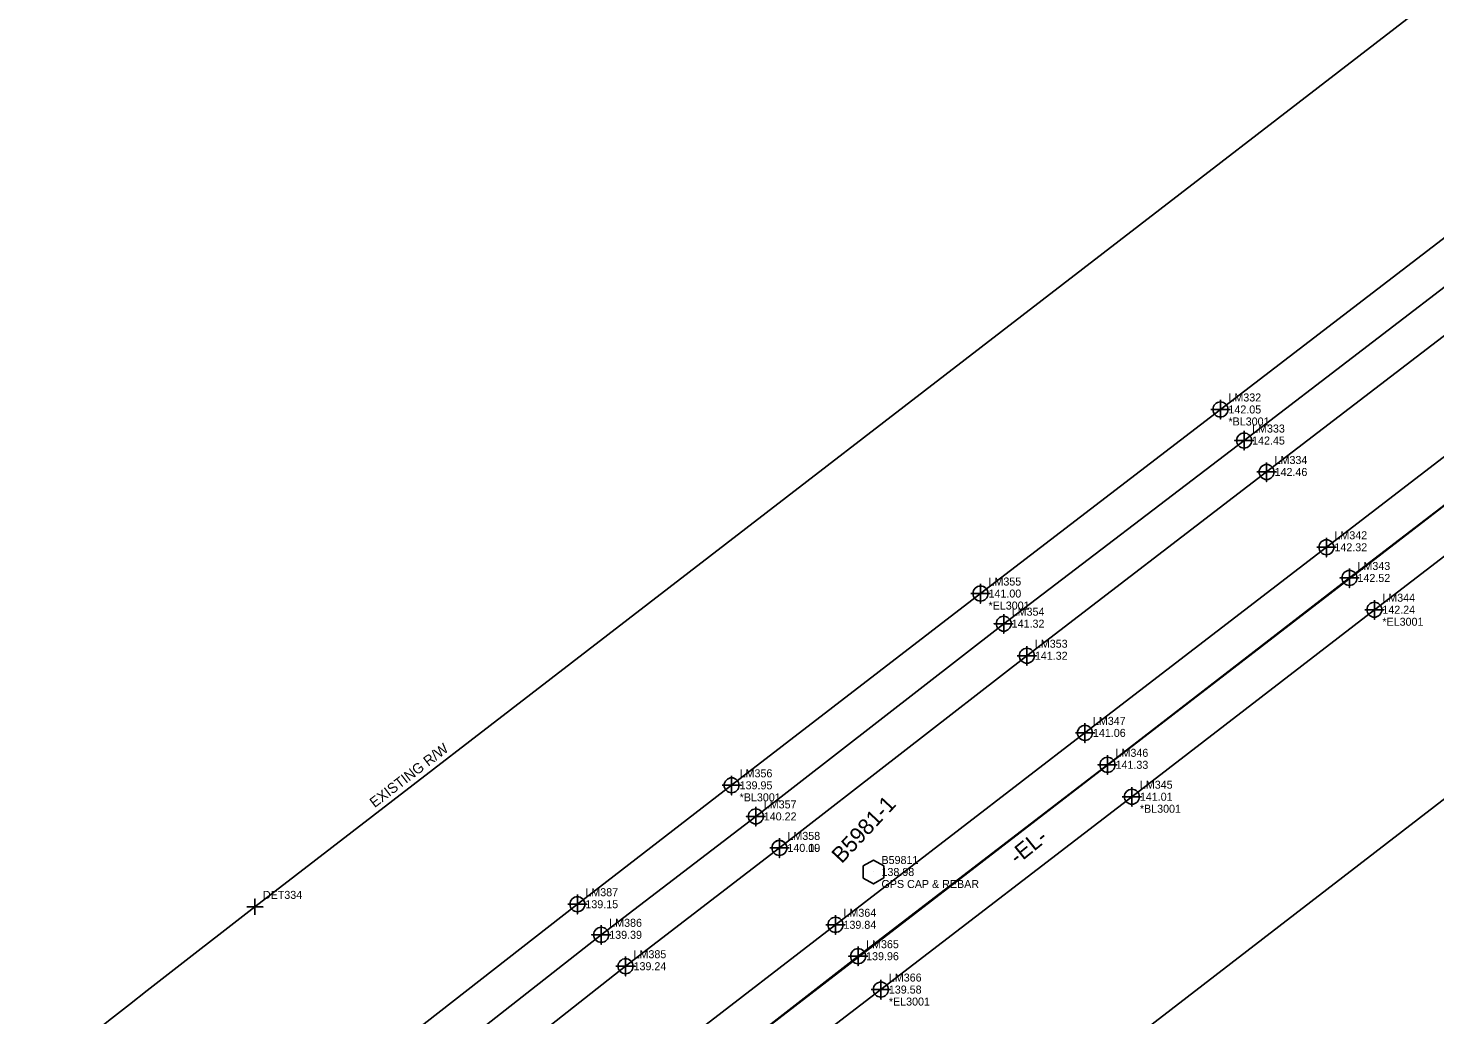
# Model space of a CAD drawing. Extents: x 2262665 to 2270527, y 505476 to 514960.
# Drawn here: x 2264417.5 to 2264856.9, y 507658 to 507966.1 of the extents above; entities that cross this region are included whole.
import ezdxf

# ---------------------------------------------------------------- set-up
doc = ezdxf.new("R2010")
doc.units = 0
for name, color, linetype in [('CTL Primary Horizontal and Vertical CELL', 7, 'Continuous'), ('CTL Primary Horizontal and Vertical Cogo Comment', 7, 'Continuous'), ('CTL Primary Horizontal and Vertical Cogo Elevation', 7, 'Continuous'), ('CTL Primary Horizontal and Vertical Cogo Number', 7, 'Continuous'), ('CTL Primary Horizontal and Vertical Text', 7, 'Continuous'), ('Exist Horizontal Alignment', 7, 'Continuous'), ('Exist Horizontal Alignment Direction Label', 7, 'Continuous'), ('Exist Property Corner CELL', 7, 'Continuous'), ('Exist Property Corner Cogo Number', 7, 'Continuous'), ('Exist Right of Way Control of Access Line', 7, 'Continuous'), ('Exist Right of Way Control of Access Line Text', 7, 'Continuous'), ('Exist Roads EOP', 7, 'Continuous'), ('Exist Roads EOP Cogo Comment', 7, 'Continuous'), ('Exist Roads EOP Cogo Elevation', 7, 'Continuous'), ('Exist Roads EOP Cogo Number', 7, 'Continuous'), ('Exist Roads EOP Cogo Point CELL', 7, 'Continuous'), ('Exist Roads EOT', 7, 'Continuous'), ('Exist Roads EOT Cogo Elevation', 7, 'Continuous'), ('Exist Roads EOT Cogo Number', 7, 'Continuous'), ('Exist Roads EOT Cogo Point CELL', 7, 'Continuous')]:
    doc.layers.add(name, color=color, linetype=linetype)

msp = doc.modelspace()

# ---------------------------------------------------------------- linework, layer by layer
at = {"layer": 'CTL Primary Horizontal and Vertical CELL'}
msp.add_line((2264681.56, 507702.6), (2264681.56, 507702.6), dxfattribs=at)
msp.add_lwpolyline([(2264678.33, 507704.47), (2264681.58, 507706.28), (2264684.83, 507704.49), (2264684.78, 507700.77), (2264681.53, 507698.88), (2264678.33, 507700.69)], close=True, dxfattribs=at)
at = {"layer": 'Exist Horizontal Alignment'}
msp.add_line((2264563.6, 507588.78), (2265116.51, 508014.84), dxfattribs=at)
at = {"layer": 'Exist Property Corner CELL'}
msp.add_line((2264488.37, 507691.7), (2264488.37, 507691.7), dxfattribs=at)
msp.add_lwpolyline([(2264485.87, 507691.7), (2264490.87, 507691.7), (2264488.37, 507691.7), (2264488.37, 507694.2), (2264488.37, 507689.2)], dxfattribs=at)
at = {"layer": 'Exist Right of Way Control of Access Line'}
for p, q in [((2264488.37, 507691.7), (2265038.72, 508115.78)), ((2264610.44, 507533.27), (2265160.79, 507957.36))]:
    msp.add_line(p, q, dxfattribs=at)
msp.add_arc((2268046.88, 503073.7), 5830, 127.616931, 136.535841, dxfattribs=at)
at = {"layer": 'Exist Roads EOP'}
msp.add_line((2264638.26, 507631.12), (2264683.86, 507665.88), dxfattribs=at)
for points in [[(2264604.13, 507673.17), (2264652.18, 507710.12), (2264729.46, 507770.12), (2264804.34, 507827.5), (2264878.61, 507884.49), (2264953.4, 507941.83), (2265025.73, 507997.77), (2265100.61, 508055.34), (2265175.62, 508113.68), (2265249.21, 508173.29), (2265321.97, 508235.58), (2265396.59, 508304.14), (2265463.32, 508369.68), (2265525.52, 508435.63), (2265587.08, 508505.56), (2265646.09, 508576.73), (2265702.44, 508648.91), (2265758.48, 508726.47), (2265812.43, 508805.68)], [(2264622.96, 507650.09), (2264669.69, 507686.11), (2264747.6, 507746.03), (2264823.02, 507803.99), (2264895.49, 507859.73), (2264970.56, 507917.69), (2265042.91, 507973.75), (2265117.63, 508031.26), (2265192.77, 508089.56), (2265267.51, 508149.88), (2265340.79, 508212.44), (2265416.18, 508281.7), (2265483.07, 508347.24), (2265547.56, 508415.53), (2265609.81, 508485.51), (2265669.26, 508556.91), (2265726.09, 508630), (2265782.72, 508708.15), (2265836.53, 508788.04)], [(2264589.08, 507692.53), (2264637.26, 507729.66), (2264714.99, 507789.55), (2264789.92, 507847.03), (2264863.62, 507903.58), (2264937.94, 507960.85), (2265012.05, 508017.75), (2265086.27, 508074.98), (2265160.63, 508133.38), (2265234.21, 508192.54), (2265306.16, 508254.54), (2265379.88, 508321.65), (2265446.65, 508386.97), (2265507.93, 508452.08), (2265569.21, 508521.55), (2265627.59, 508592.93), (2265683.12, 508664.16), (2265738.79, 508741.02), (2265756.07, 508766.2)], [(2265684.68, 508536.79), (2265628.24, 508469.05), (2265566.02, 508398.87), (2265500.44, 508329.56), (2265432.73, 508263.15), (2265356.77, 508193.7), (2265282.75, 508130.52), (2265207.97, 508070.47), (2265132.61, 508011.69), (2265056.74, 507953.11), (2264985.01, 507897.76), (2264909.79, 507839.57), (2264837.99, 507784.49), (2264762.26, 507726.1), (2264683.86, 507665.88)], [(2264347.62, 507500.85), (2264430.75, 507568.3), (2264507.06, 507628.54), (2264589.08, 507692.53)], [(2264604.13, 507673.17), (2264562.81, 507640.63), (2264531.82, 507610.73), (2264528.44, 507606.94), (2264527.86, 507605.1), (2264529.23, 507598.57), (2264534.6, 507593.15), (2264539.98, 507593.16), (2264585.09, 507621.23), (2264622.96, 507650.09)]]:
    msp.add_lwpolyline(points, dxfattribs=at)
at = {"layer": 'Exist Roads EOP Cogo Point CELL'}
for points in [[(2264789.92, 507850.03), (2264789.92, 507844.03), (2264789.92, 507847.03), (2264792.92, 507847.03), (2264786.92, 507847.03)], [(2264789.92, 507850.02), (2264789.92, 507844.02), (2264789.92, 507847.02), (2264792.92, 507847.02), (2264786.92, 507847.02)], [(2264804.33, 507830.5), (2264804.33, 507824.5), (2264804.33, 507827.5), (2264807.33, 507827.5), (2264801.33, 507827.5)], [(2264804.34, 507830.5), (2264804.34, 507824.5), (2264804.34, 507827.5), (2264807.34, 507827.5), (2264801.34, 507827.5)], [(2264823.02, 507806.99), (2264823.02, 507800.99), (2264823.02, 507803.99), (2264826.02, 507803.99), (2264820.02, 507803.99)], [(2264823.02, 507806.99), (2264823.02, 507800.99), (2264823.02, 507803.99), (2264826.02, 507803.99), (2264820.02, 507803.99)], [(2264714.98, 507792.54), (2264714.98, 507786.54), (2264714.98, 507789.54), (2264717.98, 507789.54), (2264711.98, 507789.54)], [(2264714.99, 507792.55), (2264714.99, 507786.55), (2264714.99, 507789.55), (2264717.99, 507789.55), (2264711.99, 507789.55)], [(2264837.99, 507787.49), (2264837.99, 507781.49), (2264837.99, 507784.49), (2264840.99, 507784.49), (2264834.99, 507784.49)], [(2264837.99, 507787.49), (2264837.99, 507781.49), (2264837.99, 507784.49), (2264840.99, 507784.49), (2264834.99, 507784.49)], [(2264729.46, 507773.12), (2264729.46, 507767.12), (2264729.46, 507770.12), (2264732.46, 507770.12), (2264726.46, 507770.12)], [(2264729.46, 507773.12), (2264729.46, 507767.12), (2264729.46, 507770.12), (2264732.46, 507770.12), (2264726.46, 507770.12)], [(2264747.6, 507749.03), (2264747.6, 507743.03), (2264747.6, 507746.03), (2264750.6, 507746.03), (2264744.6, 507746.03)], [(2264747.6, 507749.03), (2264747.6, 507743.03), (2264747.6, 507746.03), (2264750.6, 507746.03), (2264744.6, 507746.03)], [(2264637.26, 507732.66), (2264637.26, 507726.66), (2264637.26, 507729.66), (2264640.26, 507729.66), (2264634.26, 507729.66)], [(2264637.26, 507732.66), (2264637.26, 507726.66), (2264637.26, 507729.66), (2264640.26, 507729.66), (2264634.26, 507729.66)], [(2264762.26, 507729.1), (2264762.26, 507723.1), (2264762.26, 507726.1), (2264765.26, 507726.1), (2264759.26, 507726.1)], [(2264762.26, 507729.1), (2264762.26, 507723.1), (2264762.26, 507726.1), (2264765.26, 507726.1), (2264759.26, 507726.1)], [(2264652.18, 507713.11), (2264652.18, 507707.11), (2264652.18, 507710.11), (2264655.18, 507710.11), (2264649.18, 507710.11)], [(2264652.18, 507713.12), (2264652.18, 507707.12), (2264652.18, 507710.12), (2264655.18, 507710.12), (2264649.18, 507710.12)], [(2264589.08, 507695.53), (2264589.08, 507689.53), (2264589.08, 507692.53), (2264592.08, 507692.53), (2264586.08, 507692.53)], [(2264669.69, 507689.11), (2264669.69, 507683.11), (2264669.69, 507686.11), (2264672.69, 507686.11), (2264666.69, 507686.11)], [(2264669.69, 507689.11), (2264669.69, 507683.11), (2264669.69, 507686.11), (2264672.69, 507686.11), (2264666.69, 507686.11)], [(2264604.13, 507676.17), (2264604.13, 507670.17), (2264604.13, 507673.17), (2264607.13, 507673.17), (2264601.13, 507673.17)], [(2264683.86, 507668.88), (2264683.86, 507662.88), (2264683.86, 507665.88), (2264686.86, 507665.88), (2264680.86, 507665.88)], [(2264683.86, 507668.88), (2264683.86, 507662.88), (2264683.86, 507665.88), (2264686.86, 507665.88), (2264680.86, 507665.88)]]:
    msp.add_lwpolyline(points, dxfattribs=at)
for centre in [(2264789.92, 507847.02), (2264789.92, 507847.03), (2264804.33, 507827.5), (2264804.34, 507827.5), (2264823.02, 507803.99), (2264823.02, 507803.99), (2264714.98, 507789.54), (2264714.99, 507789.55), (2264837.99, 507784.49), (2264837.99, 507784.49), (2264729.46, 507770.12), (2264729.46, 507770.12), (2264747.6, 507746.03), (2264747.6, 507746.03), (2264637.26, 507729.66), (2264637.26, 507729.66), (2264762.26, 507726.1), (2264762.26, 507726.1), (2264652.18, 507710.11), (2264652.18, 507710.12), (2264589.08, 507692.53), (2264669.69, 507686.11), (2264669.69, 507686.11), (2264604.13, 507673.17), (2264683.86, 507665.88), (2264683.86, 507665.88)]:
    msp.add_circle(centre, 2.34, dxfattribs=at)
at = {"layer": 'Exist Roads EOT'}
for points in [[(2264355.6, 507490.59), (2264438.39, 507557.92), (2264515.74, 507619.63), (2264596.53, 507682.98), (2264644.8, 507719.95), (2264722.22, 507780.13), (2264797.31, 507837.32), (2264871.27, 507893.95), (2264945.98, 507951.46), (2265019.16, 508007.99), (2265093.77, 508065.17), (2265168.17, 508123.63), (2265241.66, 508182.89), (2265313.79, 508245.24), (2265388.67, 508313.15), (2265454.9, 508378.68), (2265516.64, 508444.01), (2265578.28, 508513.6), (2265637.19, 508584.7), (2265692.99, 508656.91), (2265748.78, 508733.7), (2265775.13, 508772.3)], [(2264387.25, 507447.54), (2264469.24, 507514.31), (2264548.37, 507577.38), (2264630.86, 507640.65), (2264676.76, 507676.3), (2264754.66, 507736.06), (2264830.22, 507794.41), (2264902.47, 507849.79), (2264977.44, 507907.47), (2265049.71, 507963.66), (2265125.01, 508021.39), (2265200.16, 508080.1), (2265274.69, 508140.15), (2265348.74, 508203.05), (2265424.49, 508272.43), (2265491.61, 508338.47), (2265557.1, 508407.36), (2265618.9, 508477.1), (2265678.7, 508548.94), (2265735.91, 508622.32), (2265792.76, 508700.56), (2265828.5, 508753.55)]]:
    msp.add_lwpolyline(points, dxfattribs=at)
at = {"layer": 'Exist Roads EOT Cogo Point CELL'}
for points in [[(2264797.31, 507840.32), (2264797.31, 507834.32), (2264797.31, 507837.32), (2264794.31, 507837.32), (2264800.31, 507837.32)], [(2264797.31, 507840.32), (2264797.31, 507834.32), (2264797.31, 507837.32), (2264794.31, 507837.32), (2264800.31, 507837.32)], [(2264830.22, 507797.41), (2264830.22, 507791.41), (2264830.22, 507794.41), (2264827.22, 507794.41), (2264833.22, 507794.41)], [(2264830.22, 507797.41), (2264830.22, 507791.41), (2264830.22, 507794.41), (2264827.22, 507794.41), (2264833.22, 507794.41)], [(2264722.22, 507783.13), (2264722.22, 507777.13), (2264722.22, 507780.13), (2264719.22, 507780.13), (2264725.22, 507780.13)], [(2264722.22, 507783.13), (2264722.22, 507777.13), (2264722.22, 507780.13), (2264719.22, 507780.13), (2264725.22, 507780.13)], [(2264754.66, 507739.06), (2264754.66, 507733.06), (2264754.66, 507736.06), (2264751.66, 507736.06), (2264757.66, 507736.06)], [(2264754.66, 507739.06), (2264754.66, 507733.06), (2264754.66, 507736.06), (2264751.66, 507736.06), (2264757.66, 507736.06)], [(2264644.8, 507722.95), (2264644.8, 507716.95), (2264644.8, 507719.95), (2264641.8, 507719.95), (2264647.8, 507719.95)], [(2264644.8, 507722.95), (2264644.8, 507716.95), (2264644.8, 507719.95), (2264641.8, 507719.95), (2264647.8, 507719.95)], [(2264596.53, 507685.98), (2264596.53, 507679.98), (2264596.53, 507682.98), (2264593.53, 507682.98), (2264599.53, 507682.98)], [(2264676.76, 507679.3), (2264676.76, 507673.3), (2264676.76, 507676.3), (2264673.76, 507676.3), (2264679.76, 507676.3)], [(2264676.76, 507679.3), (2264676.76, 507673.3), (2264676.76, 507676.3), (2264673.76, 507676.3), (2264679.76, 507676.3)]]:
    msp.add_lwpolyline(points, dxfattribs=at)
for centre in [(2264797.31, 507837.32), (2264797.31, 507837.32), (2264830.22, 507794.41), (2264830.22, 507794.41), (2264722.22, 507780.13), (2264722.22, 507780.13), (2264754.66, 507736.06), (2264754.66, 507736.06), (2264644.8, 507719.95), (2264644.8, 507719.95), (2264596.53, 507682.98), (2264676.76, 507676.3), (2264676.76, 507676.3)]:
    msp.add_circle(centre, 2.34, dxfattribs=at)

# ---------------------------------------------------------------- texts
at = {"layer": 'CTL Primary Horizontal and Vertical Cogo Comment'}
msp.add_text('GPS CAP & REBAR', height=2.5, dxfattribs=at).set_placement((2264684.06, 507697.6))
at = {"layer": 'CTL Primary Horizontal and Vertical Cogo Elevation'}
msp.add_text('138.98', height=2.5, dxfattribs=at).set_placement((2264684.06, 507701.35))
at = {"layer": 'CTL Primary Horizontal and Vertical Cogo Number'}
msp.add_text('B59811', height=2.5, dxfattribs=at).set_placement((2264684.06, 507705.1))
at = {"layer": 'CTL Primary Horizontal and Vertical Text'}
msp.add_text('B5981-1', height=5, rotation=47.0034, dxfattribs=at).set_placement((2264671.66, 507705))
at = {"layer": 'Exist Horizontal Alignment Direction Label'}
msp.add_text('-EL-', height=5, rotation=38.9994, dxfattribs=at).set_placement((2264726.5, 507704.73))
at = {"layer": 'Exist Property Corner Cogo Number'}
msp.add_text('DET334', height=2.5, dxfattribs=at).set_placement((2264490.87, 507694.2))
at = {"layer": 'Exist Right of Way Control of Access Line Text'}
msp.add_text('EXISTING R/W', height=3.2, rotation=37.6169, dxfattribs=at).set_placement((2264525.76, 507722.53))
at = {"layer": 'Exist Roads EOP Cogo Comment'}
for s, p in [('*BL3001', (2264792.42, 507842.02)), ('*BL3001', (2264792.42, 507842.03)), ('*EL3001', (2264717.48, 507784.54)), ('*EL3001', (2264717.49, 507784.55)), ('*EL3001', (2264840.49, 507779.49)), ('*EL3001', (2264840.49, 507779.49)), ('*BL3001', (2264639.76, 507724.66)), ('*BL3001', (2264639.76, 507724.66)), ('*BL3001', (2264764.76, 507721.1)), ('*BL3001', (2264764.76, 507721.1)), ('*EL3001', (2264686.36, 507660.88)), ('*EL3001', (2264686.36, 507660.88))]:
    msp.add_text(s, height=2.5, dxfattribs=at).set_placement(p)
at = {"layer": 'Exist Roads EOP Cogo Elevation'}
for s, p in [('142.05', (2264792.42, 507845.77)), ('142.05', (2264792.42, 507845.78)), ('142.46', (2264806.83, 507826.25)), ('142.46', (2264806.84, 507826.25)), ('142.32', (2264825.52, 507802.74)), ('142.32', (2264825.52, 507802.74)), ('141.00', (2264717.48, 507788.29)), ('141.00', (2264717.49, 507788.3)), ('142.24', (2264840.49, 507783.24)), ('142.24', (2264840.49, 507783.24)), ('141.32', (2264731.96, 507768.87)), ('141.32', (2264731.96, 507768.87)), ('141.06', (2264750.1, 507744.78)), ('141.06', (2264750.1, 507744.78)), ('139.95', (2264639.76, 507728.41)), ('139.95', (2264639.76, 507728.41)), ('141.01', (2264764.76, 507724.85)), ('141.01', (2264764.76, 507724.85)), ('140.10', (2264654.68, 507708.86)), ('140.09', (2264654.68, 507708.87)), ('139.15', (2264591.58, 507691.28)), ('139.84', (2264672.19, 507684.86)), ('139.84', (2264672.19, 507684.86)), ('139.24', (2264606.63, 507671.92)), ('139.58', (2264686.36, 507664.63)), ('139.58', (2264686.36, 507664.63))]:
    msp.add_text(s, height=2.5, dxfattribs=at).set_placement(p)
at = {"layer": 'Exist Roads EOP Cogo Number'}
for s, p in [('LM332', (2264792.42, 507849.52)), ('LM332', (2264792.42, 507849.53)), ('LM334', (2264806.83, 507830)), ('LM334', (2264806.84, 507830)), ('LM342', (2264825.52, 507806.49)), ('LM342', (2264825.52, 507806.49)), ('LM355', (2264717.48, 507792.04)), ('LM355', (2264717.49, 507792.05)), ('LM344', (2264840.49, 507786.99)), ('LM344', (2264840.49, 507786.99)), ('LM353', (2264731.96, 507772.62)), ('LM353', (2264731.96, 507772.62)), ('LM347', (2264750.1, 507748.53)), ('LM347', (2264750.1, 507748.53)), ('LM356', (2264639.76, 507732.16)), ('LM356', (2264639.76, 507732.16)), ('LM345', (2264764.76, 507728.6)), ('LM345', (2264764.76, 507728.6)), ('LM358', (2264654.68, 507712.61)), ('LM358', (2264654.68, 507712.62)), ('LM387', (2264591.58, 507695.03)), ('LM364', (2264672.19, 507688.61)), ('LM364', (2264672.19, 507688.61)), ('LM385', (2264606.63, 507675.67)), ('LM366', (2264686.36, 507668.38)), ('LM366', (2264686.36, 507668.38))]:
    msp.add_text(s, height=2.5, dxfattribs=at).set_placement(p)
at = {"layer": 'Exist Roads EOT Cogo Elevation'}
for s, p in [('142.45', (2264799.81, 507836.07)), ('142.45', (2264799.81, 507836.07)), ('142.52', (2264832.72, 507793.16)), ('142.52', (2264832.72, 507793.16)), ('141.32', (2264724.72, 507778.88)), ('141.32', (2264724.72, 507778.88)), ('141.33', (2264757.16, 507734.81)), ('141.33', (2264757.16, 507734.81)), ('140.22', (2264647.3, 507718.7)), ('140.22', (2264647.3, 507718.7)), ('139.39', (2264599.03, 507681.73)), ('139.96', (2264679.26, 507675.05)), ('139.96', (2264679.26, 507675.05))]:
    msp.add_text(s, height=2.5, dxfattribs=at).set_placement(p)
at = {"layer": 'Exist Roads EOT Cogo Number'}
for s, p in [('LM333', (2264799.81, 507839.82)), ('LM333', (2264799.81, 507839.82)), ('LM343', (2264832.72, 507796.91)), ('LM343', (2264832.72, 507796.91)), ('LM354', (2264724.72, 507782.63)), ('LM354', (2264724.72, 507782.63)), ('LM346', (2264757.16, 507738.56)), ('LM346', (2264757.16, 507738.56)), ('LM357', (2264647.3, 507722.45)), ('LM357', (2264647.3, 507722.45)), ('LM386', (2264599.03, 507685.48)), ('LM365', (2264679.26, 507678.8)), ('LM365', (2264679.26, 507678.8))]:
    msp.add_text(s, height=2.5, dxfattribs=at).set_placement(p)

doc.saveas('drawing.dxf')
